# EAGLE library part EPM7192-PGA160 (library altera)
EPM7192E MAX 7000 family
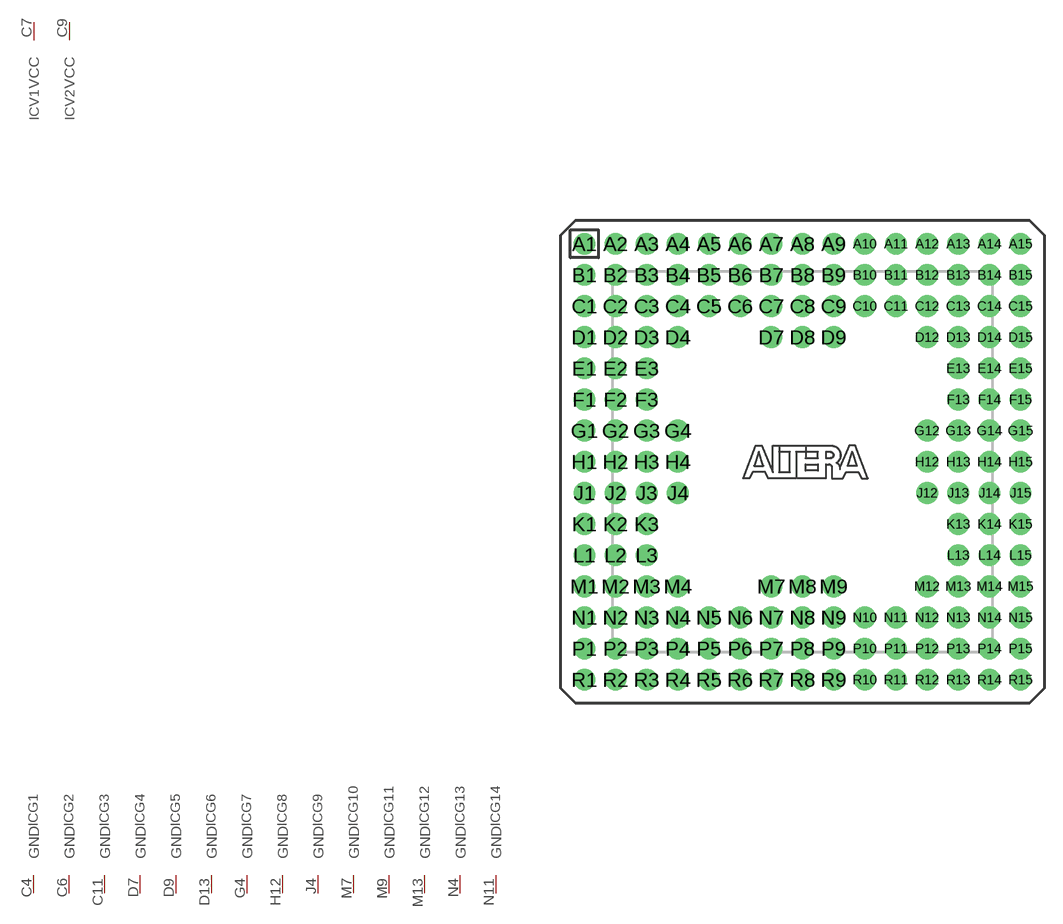
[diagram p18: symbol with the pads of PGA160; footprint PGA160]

Designator prefix IC; gates G1=GND G2=GND G3=GND G4=GND G5=GND G6=GND G7=GND G8=GND G9=GND G10=GND G11=GND G12=GND G13=GND G14=GND V1=VCCINT V2=VCCINT V3=VCCINT V4=VCCINT VO1=VCCIO VO2=VCCIO VO3=VCCIO VO4=VCCIO VO5=VCCIO VO6=VCCIO VO7=VCCIO VO8=VCCIO VO9=VCCIO VO10=VCCIO NC1=NC NC2=NC NC3=NC NC4=NC NC5=NC NC6=NC NC7=NC NC8=NC NC9=7192

## EPM7192-PGA160 (OC_FARNELL: unknown; OC_NEWARK: unknown)  [PGA160]
A1  NC1:NC  nc
A2  NC2:NC  nc
A3  NC9:IO113
A4  NC9:IO109
A5  NC9:IO105
A6  NC9:IO102
A7  NC9:IO101
A8  NC9:IO97
A9  NC9:IO83
A10  NC9:IO88
A11  NC9:IO91
A12  NC9:IO94
A13  NC9:IO96
A14  NC3:NC  nc
A15  NC4:NC  nc
B1  NC9:IO121
B2  NC9:IO120
B3  NC9:IO117
B4  NC9:IO115
B5  NC9:IO110
B6  NC9:IO107
B7  NC9:IO104
B8  NC9:IO99
B9  NC9:IO86
B10  NC9:IO89
B11  NC9:IO93
B12  NC9:IO65
B13  NC9:IO67
B14  NC9:IO70
B15  NC9:IO75
C1  NC9:IO125
C2  NC9:IO123
C3  NC9:IO118
C4  G1:GND  pwr
C5  VO1:VCCIO  pwr
C6  G2:GND  pwr
C7  V1:VCC  pwr
C8  NC9:IO85
C9  V2:VCC  pwr
C10  VO2:VCCIO  pwr
C11  G3:GND  pwr
C12  VO3:VCCIO  pwr
C13  NC9:IO69
C14  NC9:IO72
C15  NC9:IO78
D1  NC9:IO128
D2  NC9:IO126
D3  VO4:VCCIO  pwr
D4  NC9:IO112
D7  G4:GND  pwr
D8  NC9:IO81
D9  G5:GND  pwr
D12  NC9:IO73
D13  G6:GND  pwr
D14  NC9:IO77
D15  NC9:IO49
E1  NC9:IO136
E2  NC9:IO133
E3  NC9:IO129
E13  NC9:IO80
E14  NC9:IO53
E15  NC9:IO51
F1  NC9:IO139
F2  NC9:IO134
F3  NC9:IO131
F13  NC9:IO56
F14  NC9:IO59
F15  NC9:IO54
G1  NC9:IO141
G2  NC9:IO142
G3  NC9:IO137
G4  G7:GND  pwr
G12  VO5:VCCIO  pwr
G13  NC9:IO61
G14  NC9:IO57
G15  NC9:IO62
H1  NC9:IO144
H2  NC9:IO145
H3  NC9:IO149
H4  VO6:VCCIO  pwr
H12  G8:GND  pwr
H13  NC9:IO64
H14  NC9:IO33
H15  NC9:IO37
J1  NC9:IO147
J2  NC9:IO153
J3  NC9:IO150
J4  G9:GND  pwr
J12  VO7:VCCIO  pwr
J13  NC9:IO35
J14  NC9:IO40
J15  NC9:IO38
K1  NC9:IO152
K2  NC9:IO155
K3  NC9:IO157
K13  NC9:IO43
K14  NC9:IO46
K15  NC9:IO41
L1  NC9:IO158
L2  NC9:IO161
L3  NC9:IO165
L13  NC9:IO48
L14  NC9:IO17
L15  NC9:IO45
M1  NC9:IO160
M2  NC9:IO168
M3  VO8:VCCIO  pwr
M4  NC9:IO181
M7  G10:GND  pwr
M8  NC9:GCLK1  in
M9  G11:GND  pwr
M12  NC9:IO1
M13  G12:GND  pwr
M14  NC9:IO19
M15  NC9:IO21
N1  NC9:IO163
N2  NC9:IO169
N3  NC9:IO173
N4  G13:GND  pwr
N5  VO9:VCCIO  pwr
N6  NC9:IO189
N7  V3:VCC  pwr
N8  NC9:GCLR/  in
N9  V4:VCC  pwr
N10  NC9:IO9
N11  G14:GND  pwr
N12  VO10:VCCIO  pwr
N13  NC9:IO27
N14  NC9:IO22
N15  NC9:IO24
P1  NC9:IO166
P2  NC9:IO171
P3  NC9:IO174
P4  NC9:IO176
P5  NC9:IO184
P6  NC9:IO187
P7  NC9:IO192
P8  NC9:OE1  in
P9  NC9:IO14
P10  NC9:IO6
P11  NC9:IO3
P12  NC9:IO5
P13  NC9:IO30
P14  NC9:IO29
P15  NC9:IO25
R1  NC5:NC  nc
R2  NC6:NC  nc
R3  NC9:IO177
R4  NC9:IO179
R5  NC9:IO182
R6  NC9:IO185
R7  NC9:IO190
R8  NC9:OE2-GCLK2  in
R9  NC9:IO16
R10  NC9:IO13
R11  NC9:IO11
R12  NC9:IO8
R13  NC9:IO32
R14  NC7:NC  nc
R15  NC8:NC  nc

## Footprint PGA160 (pad centres in mm)
Pin Grid Array
drill 0.813 pad 1.778 round: A1 -17.78,17.78; A2 -15.24,17.78; A3 -12.7,17.78; A4 -10.16,17.78; A5 -7.62,17.78; A6 -5.08,17.78; A7 -2.54,17.78; A8 0,17.78; A9 2.54,17.78; A10 5.08,17.78; A11 7.62,17.78; A12 10.16,17.78; A13 12.7,17.78; A14 15.24,17.78; A15 17.78,17.78; B1 -17.78,15.24; B2 -15.24,15.24; B3 -12.7,15.24; B4 -10.16,15.24; B5 -7.62,15.24; B6 -5.08,15.24; B7 -2.54,15.24; B8 0,15.24; B9 2.54,15.24; B10 5.08,15.24; B11 7.62,15.24; B12 10.16,15.24; B13 12.7,15.24; B14 15.24,15.24; B15 17.78,15.24; C1 -17.78,12.7; C2 -15.24,12.7; C3 -12.7,12.7; C4 -10.16,12.7; C5 -7.62,12.7; C6 -5.08,12.7; C7 -2.54,12.7; C8 0,12.7; C9 2.54,12.7; C10 5.08,12.7; C11 7.62,12.7; C12 10.16,12.7; C13 12.7,12.7; C14 15.24,12.7; C15 17.78,12.7; D1 -17.78,10.16; D2 -15.24,10.16; D3 -12.7,10.16; D4 -10.16,10.16; D7 -2.54,10.16; D8 0,10.16; D9 2.54,10.16; D12 10.16,10.16; D13 12.7,10.16; D14 15.24,10.16; D15 17.78,10.16; E1 -17.78,7.62; E2 -15.24,7.62; E3 -12.7,7.62; E13 12.7,7.62; E14 15.24,7.62; E15 17.78,7.62; F1 -17.78,5.08; F2 -15.24,5.08; F3 -12.7,5.08; F13 12.7,5.08; F14 15.24,5.08; F15 17.78,5.08; G1 -17.78,2.54; G2 -15.24,2.54; G3 -12.7,2.54; G4 -10.16,2.54; G12 10.16,2.54; G13 12.7,2.54; G14 15.24,2.54; G15 17.78,2.54; H1 -17.78,0; H2 -15.24,0; H3 -12.7,0; H4 -10.16,0; H12 10.16,0; H13 12.7,0; H14 15.24,0; H15 17.78,0; J1 -17.78,-2.54; J2 -15.24,-2.54; J3 -12.7,-2.54; J4 -10.16,-2.54; J12 10.16,-2.54; J13 12.7,-2.54; J14 15.24,-2.54; J15 17.78,-2.54; K1 -17.78,-5.08; K2 -15.24,-5.08; K3 -12.7,-5.08; K13 12.7,-5.08; K14 15.24,-5.08; K15 17.78,-5.08; L1 -17.78,-7.62; L2 -15.24,-7.62; L3 -12.7,-7.62; L13 12.7,-7.62; L14 15.24,-7.62; L15 17.78,-7.62; M1 -17.78,-10.16; M2 -15.24,-10.16; M3 -12.7,-10.16; M4 -10.16,-10.16; M7 -2.54,-10.16; M8 0,-10.16; M9 2.54,-10.16; M12 10.16,-10.16; M13 12.7,-10.16; M14 15.24,-10.16; M15 17.78,-10.16; N1 -17.78,-12.7; N2 -15.24,-12.7; N3 -12.7,-12.7; N4 -10.16,-12.7; N5 -7.62,-12.7; N6 -5.08,-12.7; N7 -2.54,-12.7; N8 0,-12.7; N9 2.54,-12.7; N10 5.08,-12.7; N11 7.62,-12.7; N12 10.16,-12.7; N13 12.7,-12.7; N14 15.24,-12.7; N15 17.78,-12.7; P1 -17.78,-15.24; P2 -15.24,-15.24; P3 -12.7,-15.24; P4 -10.16,-15.24; P5 -7.62,-15.24; P6 -5.08,-15.24; P7 -2.54,-15.24; P8 0,-15.24; P9 2.54,-15.24; P10 5.08,-15.24; P11 7.62,-15.24; P12 10.16,-15.24; P13 12.7,-15.24; P14 15.24,-15.24; P15 17.78,-15.24; R1 -17.78,-17.78; R2 -15.24,-17.78; R3 -12.7,-17.78; R4 -10.16,-17.78; R5 -7.62,-17.78; R6 -5.08,-17.78; R7 -2.54,-17.78; R8 0,-17.78; R9 2.54,-17.78; R10 5.08,-17.78; R11 7.62,-17.78; R12 10.16,-17.78; R13 12.7,-17.78; R14 15.24,-17.78; R15 17.78,-17.78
